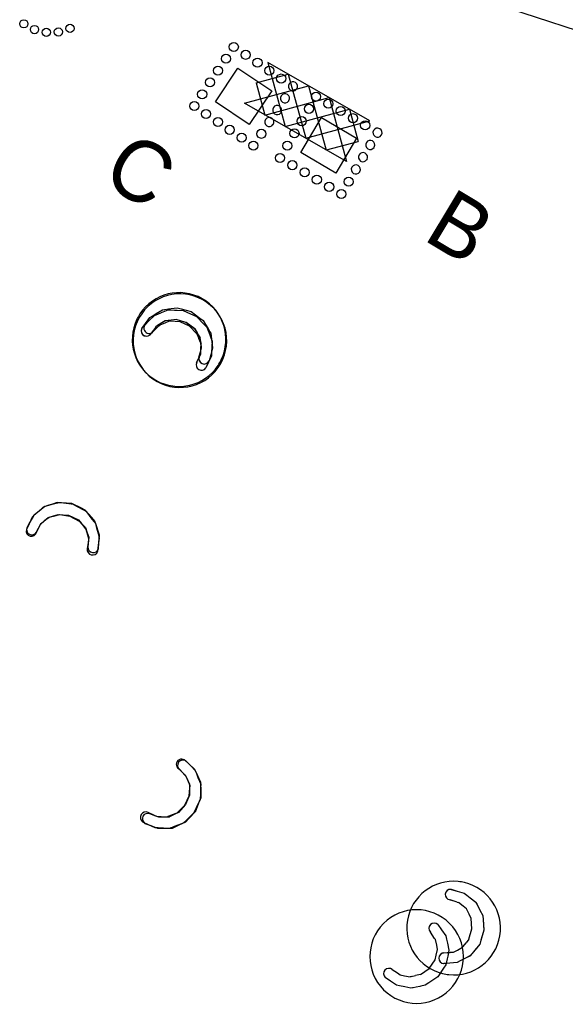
# Model space of a CAD drawing. Extents: x 2283629 to 2286552, y 529718 to 531440.
# Drawn here: x 2284499.9 to 2284634, y 530595.4 to 530837.2 of the extents above; entities that cross this region are included whole.
import ezdxf

# ---------------------------------------------------------------- set-up
doc = ezdxf.new("R2010")
doc.units = 0
for name, color, linetype in [('Draft_Corridor_Graphics_Final', 7, 'Continuous'), ('Draft_RDY_Construction_Class_Element', 7, 'Continuous'), ('P_NCDOT_Terrain_Model_Contour_Major', 7, 'Continuous'), ('P_NCDOT_Terrain_Model_Contour_Minor', 7, 'Continuous'), ('P_NCDOT_Terrain_Model_Triangles', 7, 'Continuous'), ('P_NCDOT_Terrain_Points_Random', 7, 'Continuous'), ('P_NCDOT_Terrain_Void', 7, 'Continuous'), ('P_RDY_TC_Pvmt_Asphalt_Intermediate_Course', 7, 'Continuous'), ('P_RDY_TC_Pvmt_Asphalt_Surface_Course', 7, 'Continuous'), ('P_RDY_TC_Pvmt_Asphalt_Surface_Course_Wedge', 7, 'Continuous')]:
    doc.layers.add(name, color=color, linetype=linetype)

msp = doc.modelspace()

# ---------------------------------------------------------------- linework, layer by layer
at = {"layer": 'Draft_Corridor_Graphics_Final'}
for p, q in [((2284511.89, 530715.37), (2284511.9, 530715.36)), ((2284514.29, 530714.25), (2284515.1, 530713.38)), ((2284504.83, 530712.85), (2284504.97, 530713.15)), ((2284515.86, 530712.57), (2284516.02, 530712.4)), ((2284540.33, 530651.76), (2284540.58, 530651.53)), ((2284540.66, 530644.26), (2284540.66, 530644.25)), ((2284536.82, 530641.29), (2284536.61, 530641.19)), ((2284538.89, 530642.3), (2284537.82, 530641.78))]:
    msp.add_line(p, q, dxfattribs=at)
for points in [[(2284519.25, 530707.16), (2284519.36, 530708.7), (2284519.48, 530710.45), (2284519.24, 530711.22), (2284518.82, 530712.5), (2284518.36, 530713.94), (2284518.36, 530713.95), (2284518.11, 530714.22), (2284518, 530714.35), (2284517.52, 530714.9), (2284516.88, 530715.62), (2284516.72, 530715.79), (2284515.97, 530716.64), (2284515.04, 530717.09), (2284512.67, 530718.24), (2284512.66, 530718.24), (2284510.12, 530718.43), (2284509.08, 530718.5), (2284507.68, 530718.04), (2284507.05, 530717.84), (2284506.14, 530717.54), (2284506.07, 530717.51), (2284505.65, 530717.37), (2284505.61, 530717.36), (2284504.29, 530716.15), (2284503.54, 530715.47), (2284502.93, 530714.9), (2284502.16, 530713.25), (2284501.51, 530711.84)], [(2284504.02, 530711.17), (2284504.83, 530712.85), (2284504.97, 530713.15), (2284506.07, 530714.14), (2284506.83, 530714.83), (2284508.21, 530715.25), (2284509.36, 530715.6), (2284511.89, 530715.37), (2284511.9, 530715.36), (2284514.29, 530714.25), (2284515.1, 530713.38), (2284515.86, 530712.57), (2284516.02, 530712.4), (2284516.48, 530711.02), (2284516.83, 530709.98), (2284516.77, 530709.19), (2284516.64, 530707.64), (2284516.64, 530707.64)], [(2284530.65, 530639.64), (2284532.09, 530639.09), (2284533.73, 530638.45), (2284534.54, 530638.46), (2284535.88, 530638.48), (2284537.39, 530638.5), (2284537.4, 530638.5), (2284537.73, 530638.65), (2284537.89, 530638.72), (2284538.56, 530639.02), (2284539.43, 530639.42), (2284539.65, 530639.52), (2284540.68, 530639.99), (2284541.38, 530640.74), (2284543.17, 530642.67), (2284543.18, 530642.68), (2284544.11, 530645.06), (2284544.49, 530646.03), (2284544.46, 530647.49), (2284544.45, 530648.16), (2284544.43, 530649.11), (2284544.43, 530649.19), (2284544.42, 530649.63), (2284544.42, 530649.67), (2284543.65, 530651.29), (2284543.22, 530652.21), (2284542.86, 530652.96), (2284541.51, 530654.18), (2284540.35, 530655.22)], [(2284538.97, 530653.02), (2284540.33, 530651.76), (2284540.58, 530651.53), (2284541.21, 530650.19), (2284541.64, 530649.26), (2284541.64, 530647.81), (2284541.63, 530646.61), (2284540.66, 530644.26), (2284540.66, 530644.25), (2284538.89, 530642.3), (2284537.82, 530641.78), (2284536.82, 530641.29), (2284536.61, 530641.19), (2284535.16, 530641.15), (2284534.06, 530641.13), (2284533.32, 530641.42), (2284531.88, 530642), (2284531.88, 530642)]]:
    msp.add_lwpolyline(points, dxfattribs=at)
for centre, radius, start, end in [((2284502.76, 530711.5), 1.3, 165.0476, 345.0476), ((2284517.97, 530707.5), 1.33, 173.9349, 345.0476), ((2284539.66, 530654.12), 1.3, 57.9198, 237.9198), ((2284531.35, 530640.77), 1.33, 66.8072, 237.9198)]:
    msp.add_arc(centre, radius, start, end, dxfattribs=at)
at = {"layer": 'P_NCDOT_Terrain_Model_Contour_Major'}
for p, q in [((2284533.33, 530761.61), (2284533.52, 530761.88)), ((2284533.34, 530761.61), (2284533.53, 530761.88)), ((2284534.79, 530762.65), (2284533.52, 530761.88)), ((2284534.8, 530762.65), (2284533.53, 530761.88)), ((2284535.67, 530763.19), (2284534.79, 530762.65)), ((2284535.68, 530763.18), (2284534.8, 530762.65)), ((2284537.1, 530763.34), (2284535.67, 530763.19)), ((2284537.11, 530763.33), (2284535.68, 530763.18)), ((2284538.3, 530763.46), (2284537.1, 530763.34)), ((2284538.31, 530763.46), (2284537.11, 530763.33)), ((2284540.74, 530762.76), (2284538.3, 530763.46)), ((2284540.75, 530762.75), (2284538.31, 530763.46)), ((2284540.74, 530762.76), (2284540.75, 530762.75)), ((2284540.75, 530762.75), (2284540.76, 530762.75)), ((2284542.88, 530761.21), (2284540.75, 530762.75)), ((2284542.89, 530761.2), (2284540.76, 530762.75)), ((2284533.33, 530761.61), (2284532.22, 530760.12)), ((2284533.34, 530761.61), (2284532.23, 530760.12)), ((2284542.88, 530761.21), (2284543.52, 530760.2)), ((2284542.89, 530761.2), (2284543.53, 530760.2)), ((2284544.11, 530759.26), (2284543.52, 530760.2)), ((2284544.12, 530759.26), (2284543.53, 530760.2)), ((2284544.11, 530759.26), (2284544.24, 530759.06)), ((2284544.12, 530759.26), (2284544.25, 530759.06)), ((2284544.43, 530757.62), (2284544.24, 530759.06)), ((2284544.44, 530757.62), (2284544.25, 530759.06)), ((2284544.58, 530756.53), (2284544.43, 530757.62)), ((2284544.59, 530756.52), (2284544.44, 530757.62)), ((2284543.94, 530754.27), (2284544.36, 530755.77)), ((2284543.95, 530754.27), (2284544.37, 530755.76)), ((2284544.36, 530755.77), (2284544.58, 530756.53)), ((2284544.37, 530755.76), (2284544.59, 530756.52)), ((2284607.43, 530620.3), (2284605.64, 530620.83)), ((2284607.43, 530620.31), (2284605.65, 530620.84)), ((2284607.43, 530620.31), (2284607.75, 530620.22)), ((2284607.43, 530620.3), (2284607.75, 530620.2)), ((2284608.9, 530619.29), (2284607.75, 530620.22)), ((2284608.9, 530619.28), (2284607.75, 530620.2)), ((2284609.71, 530618.65), (2284608.9, 530619.29)), ((2284609.71, 530618.64), (2284608.9, 530619.28)), ((2284610.34, 530617.35), (2284609.71, 530618.65)), ((2284610.34, 530617.34), (2284609.71, 530618.64)), ((2284610.87, 530616.27), (2284610.34, 530617.35)), ((2284610.87, 530616.26), (2284610.34, 530617.34)), ((2284611.04, 530613.73), (2284610.87, 530616.27)), ((2284611.04, 530613.72), (2284610.87, 530616.26)), ((2284610.31, 530611.19), (2284611.04, 530613.72)), ((2284610.31, 530611.18), (2284611.03, 530613.71)), ((2284611.04, 530613.72), (2284611.03, 530613.71)), ((2284611.04, 530613.73), (2284611.04, 530613.72)), ((2284608.9, 530609.36), (2284609.59, 530610.24)), ((2284608.91, 530609.37), (2284609.59, 530610.25)), ((2284610.31, 530611.19), (2284609.59, 530610.25)), ((2284610.31, 530611.18), (2284609.59, 530610.24)), ((2284604.16, 530607.82), (2284605.71, 530607.94)), ((2284604.16, 530607.81), (2284605.71, 530607.93)), ((2284605.71, 530607.94), (2284606.5, 530608)), ((2284605.71, 530607.93), (2284606.5, 530607.99)), ((2284606.5, 530608), (2284607.48, 530608.51)), ((2284606.5, 530607.99), (2284607.47, 530608.5)), ((2284607.47, 530608.5), (2284608.76, 530609.18)), ((2284607.48, 530608.51), (2284608.76, 530609.19)), ((2284608.91, 530609.37), (2284608.76, 530609.19)), ((2284608.9, 530609.36), (2284608.76, 530609.18))]:
    msp.add_line(p, q, dxfattribs=at)
for points in [[(2284529.88, 530761.25), (2284530.79, 530762.52), (2284531.85, 530763.99), (2284532.56, 530764.43), (2284533.42, 530764.96), (2284534.95, 530765.9), (2284534.99, 530765.9), (2284535.43, 530765.96), (2284535.51, 530765.97), (2284536.45, 530766.09), (2284537.11, 530766.18), (2284538.57, 530766.36), (2284539.57, 530766.09), (2284542.04, 530765.43), (2284542.05, 530765.42), (2284544.16, 530763.85), (2284544.99, 530763.24), (2284545.56, 530762.26), (2284545.69, 530762.06), (2284546.18, 530761.23), (2284546.55, 530760.6), (2284546.63, 530760.45), (2284546.82, 530760.14), (2284546.82, 530760.13), (2284547.01, 530758.63), (2284547.17, 530757.3), (2284547.27, 530756.49), (2284546.82, 530754.8), (2284546.42, 530753.3)], [(2284529.89, 530761.25), (2284530.8, 530762.51), (2284531.86, 530763.99), (2284532.57, 530764.43), (2284533.43, 530764.95), (2284534.96, 530765.89), (2284535, 530765.9), (2284535.44, 530765.96), (2284535.52, 530765.97), (2284536.46, 530766.09), (2284537.12, 530766.17), (2284538.58, 530766.36), (2284539.58, 530766.09), (2284542.05, 530765.42), (2284542.06, 530765.42), (2284544.17, 530763.85), (2284545, 530763.23), (2284545.58, 530762.26), (2284545.7, 530762.05), (2284546.19, 530761.23), (2284546.56, 530760.6), (2284546.64, 530760.45), (2284546.83, 530760.13), (2284546.83, 530760.13), (2284547.02, 530758.63), (2284547.18, 530757.29), (2284547.28, 530756.49), (2284546.83, 530754.79), (2284546.43, 530753.3)], [(2284605.91, 530623.41), (2284607.41, 530622.99), (2284609.16, 530622.5), (2284609.81, 530621.98), (2284610.61, 530621.35), (2284612.01, 530620.24), (2284612.03, 530620.2), (2284612.23, 530619.81), (2284612.27, 530619.74), (2284612.71, 530618.89), (2284613.01, 530618.3), (2284613.68, 530617), (2284613.78, 530615.96), (2284613.99, 530613.42), (2284613.99, 530613.41), (2284613.24, 530610.88), (2284612.94, 530609.9), (2284612.22, 530609.02), (2284612.07, 530608.84), (2284611.46, 530608.09), (2284611, 530607.53), (2284610.89, 530607.4), (2284610.66, 530607.11), (2284610.65, 530607.11), (2284609.3, 530606.42), (2284608.11, 530605.82), (2284607.39, 530605.45), (2284605.64, 530605.29), (2284604.09, 530605.15)], [(2284605.91, 530623.43), (2284607.41, 530623), (2284609.16, 530622.51), (2284609.81, 530621.99), (2284610.61, 530621.36), (2284612.01, 530620.25), (2284612.03, 530620.21), (2284612.23, 530619.82), (2284612.27, 530619.75), (2284612.71, 530618.9), (2284613.01, 530618.31), (2284613.69, 530617.01), (2284613.78, 530615.97), (2284613.99, 530613.43), (2284613.99, 530613.42), (2284613.24, 530610.89), (2284612.94, 530609.91), (2284612.22, 530609.03), (2284612.07, 530608.85), (2284611.46, 530608.1), (2284611, 530607.54), (2284610.89, 530607.41), (2284610.66, 530607.12), (2284610.65, 530607.12), (2284609.31, 530606.44), (2284608.11, 530605.83), (2284607.39, 530605.46), (2284605.64, 530605.3), (2284604.1, 530605.16)]]:
    msp.add_lwpolyline(points, dxfattribs=at)
for centre, radius, start, end in [((2284539.06, 530758.6), 11.5, 334.1603, 146.8069), ((2284539.04, 530758.55), 11.5, 146.5657, 154.1603), ((2284539.04, 530758.55), 11.5, 154.1603, 326.5657), ((2284531.05, 530760.69), 1.3, 154.1603, 334.1603), ((2284531.06, 530760.68), 1.3, 154.1603, 334.1603), ((2284545.22, 530753.88), 1.33, 163.0477, 334.1603), ((2284545.23, 530753.88), 1.33, 163.0477, 334.1603), ((2284539.06, 530758.6), 11.5, 326.3245, 334.1603), ((2284606.51, 530613.9), 11.5, 84.1603, 256.5657), ((2284606.55, 530613.89), 11.5, 264.1603, 76.8069), ((2284606.51, 530613.9), 11.5, 76.5657, 84.1603), ((2284605.78, 530622.13), 1.3, 84.1603, 264.1603), ((2284605.78, 530622.12), 1.3, 84.1603, 264.1603), ((2284604.23, 530606.48), 1.33, 93.0477, 264.1603), ((2284604.23, 530606.49), 1.33, 93.0477, 264.1603), ((2284606.55, 530613.89), 11.5, 256.3245, 264.1603)]:
    msp.add_arc(centre, radius, start, end, dxfattribs=at)
at = {"layer": 'P_NCDOT_Terrain_Model_Contour_Minor'}
for p, q in [((2284534.09, 530761.91), (2284532.75, 530760.61)), ((2284534.09, 530761.91), (2284532.75, 530760.61)), ((2284534.09, 530761.91), (2284534.33, 530762.14)), ((2284534.09, 530761.91), (2284534.33, 530762.14)), ((2284535.7, 530762.69), (2284534.33, 530762.14)), ((2284535.7, 530762.69), (2284534.33, 530762.14)), ((2284536.65, 530763.08), (2284535.7, 530762.69)), ((2284536.65, 530763.08), (2284535.7, 530762.69)), ((2284538.1, 530763), (2284536.65, 530763.08)), ((2284538.1, 530763), (2284536.65, 530763.08)), ((2284539.3, 530762.93), (2284538.1, 530763)), ((2284539.3, 530762.93), (2284538.1, 530763)), ((2284541.59, 530761.83), (2284539.3, 530762.93)), ((2284541.59, 530761.83), (2284539.3, 530762.93)), ((2284541.59, 530761.83), (2284541.6, 530761.82)), ((2284541.59, 530761.83), (2284541.6, 530761.82)), ((2284543.45, 530759.95), (2284541.6, 530761.82)), ((2284543.45, 530759.95), (2284541.6, 530761.82)), ((2284543.45, 530759.95), (2284543.92, 530758.86)), ((2284543.45, 530759.95), (2284543.92, 530758.86)), ((2284544.35, 530757.83), (2284543.92, 530758.86)), ((2284544.35, 530757.83), (2284543.92, 530758.86)), ((2284544.35, 530757.83), (2284544.44, 530757.62)), ((2284544.35, 530757.83), (2284544.44, 530757.62)), ((2284544.4, 530756.17), (2284544.44, 530757.62)), ((2284544.4, 530756.17), (2284544.44, 530757.62)), ((2284544.03, 530754.35), (2284544.36, 530755.06)), ((2284544.03, 530754.35), (2284544.36, 530755.06)), ((2284544.36, 530755.06), (2284544.4, 530756.17)), ((2284544.36, 530755.06), (2284544.4, 530756.17)), ((2284543.37, 530752.94), (2284544.03, 530754.35)), ((2284543.37, 530752.94), (2284544.03, 530754.35)), ((2284601.87, 530611.38), (2284600.82, 530612.92)), ((2284601.87, 530611.38), (2284600.82, 530612.92)), ((2284601.87, 530611.38), (2284602.06, 530611.11)), ((2284601.87, 530611.38), (2284602.06, 530611.11)), ((2284602.37, 530609.66), (2284602.06, 530611.11)), ((2284602.37, 530609.66), (2284602.06, 530611.11)), ((2284602.59, 530608.66), (2284602.37, 530609.66)), ((2284602.59, 530608.66), (2284602.37, 530609.66)), ((2284601.99, 530606.08), (2284602.26, 530607.25)), ((2284601.99, 530606.08), (2284602.26, 530607.25)), ((2284602.26, 530607.25), (2284602.59, 530608.66)), ((2284602.26, 530607.25), (2284602.59, 530608.66)), ((2284600.52, 530604), (2284601.99, 530606.08)), ((2284600.52, 530604), (2284601.99, 530606.08)), ((2284591.46, 530603.75), (2284592.73, 530602.87)), ((2284591.46, 530603.75), (2284592.73, 530602.87)), ((2284592.73, 530602.87), (2284593.38, 530602.42)), ((2284592.73, 530602.87), (2284593.38, 530602.42)), ((2284593.38, 530602.42), (2284594.46, 530602.2)), ((2284593.38, 530602.42), (2284594.46, 530602.2)), ((2284594.46, 530602.2), (2284595.89, 530601.91)), ((2284594.46, 530602.2), (2284595.89, 530601.91)), ((2284596.11, 530601.96), (2284597.2, 530602.21)), ((2284596.11, 530601.96), (2284597.2, 530602.21)), ((2284598.36, 530602.49), (2284597.2, 530602.21)), ((2284598.36, 530602.49), (2284597.2, 530602.21)), ((2284598.36, 530602.49), (2284600.51, 530604)), ((2284598.36, 530602.49), (2284600.51, 530604)), ((2284600.52, 530604), (2284600.51, 530604)), ((2284600.52, 530604), (2284600.51, 530604)), ((2284596.11, 530601.96), (2284595.89, 530601.91)), ((2284596.11, 530601.96), (2284595.89, 530601.91))]:
    msp.add_line(p, q, dxfattribs=at)
for points in [[(2284530.63, 530762.11), (2284531.73, 530763.21), (2284533.02, 530764.49), (2284533.79, 530764.81), (2284534.73, 530765.19), (2284536.39, 530765.87), (2284536.43, 530765.87), (2284536.87, 530765.85), (2284536.95, 530765.85), (2284537.9, 530765.82), (2284538.57, 530765.8), (2284540.03, 530765.74), (2284540.98, 530765.31), (2284543.3, 530764.26), (2284543.31, 530764.25), (2284545.14, 530762.36), (2284545.86, 530761.61), (2284546.27, 530760.56), (2284546.36, 530760.34), (2284546.71, 530759.44), (2284546.97, 530758.76), (2284547.03, 530758.6), (2284547.17, 530758.26), (2284547.17, 530758.25), (2284547.1, 530756.74), (2284547.05, 530755.4), (2284547.01, 530754.59), (2284546.29, 530752.99), (2284545.66, 530751.58)], [(2284530.63, 530762.11), (2284531.73, 530763.21), (2284533.02, 530764.49), (2284533.79, 530764.81), (2284534.73, 530765.19), (2284536.39, 530765.87), (2284536.43, 530765.87), (2284536.87, 530765.85), (2284536.95, 530765.85), (2284537.9, 530765.82), (2284538.57, 530765.8), (2284540.03, 530765.74), (2284540.98, 530765.31), (2284543.3, 530764.26), (2284543.31, 530764.25), (2284545.14, 530762.36), (2284545.86, 530761.61), (2284546.27, 530760.56), (2284546.36, 530760.34), (2284546.71, 530759.44), (2284546.97, 530758.76), (2284547.03, 530758.6), (2284547.17, 530758.26), (2284547.17, 530758.25), (2284547.1, 530756.74), (2284547.05, 530755.4), (2284547.01, 530754.59), (2284546.29, 530752.99), (2284545.66, 530751.58)], [(2284602.65, 530614.76), (2284603.55, 530613.48), (2284604.6, 530612), (2284604.78, 530611.18), (2284605, 530610.2), (2284605.38, 530608.44), (2284605.38, 530608.4), (2284605.29, 530607.97), (2284605.27, 530607.9), (2284605.08, 530606.96), (2284604.94, 530606.31), (2284604.64, 530604.88), (2284604.06, 530604.01), (2284602.62, 530601.9), (2284602.62, 530601.9), (2284600.43, 530600.41), (2284599.58, 530599.83), (2284598.48, 530599.61), (2284598.24, 530599.56), (2284597.3, 530599.37), (2284596.59, 530599.22), (2284596.42, 530599.19), (2284596.06, 530599.11), (2284596.05, 530599.11), (2284594.57, 530599.43), (2284593.26, 530599.71), (2284592.47, 530599.89), (2284591.01, 530600.87), (2284589.73, 530601.73)], [(2284602.65, 530614.76), (2284603.55, 530613.48), (2284604.6, 530612), (2284604.78, 530611.18), (2284605, 530610.2), (2284605.38, 530608.44), (2284605.38, 530608.4), (2284605.29, 530607.97), (2284605.27, 530607.9), (2284605.08, 530606.96), (2284604.94, 530606.31), (2284604.64, 530604.88), (2284604.06, 530604.01), (2284602.62, 530601.9), (2284602.62, 530601.9), (2284600.43, 530600.41), (2284599.58, 530599.83), (2284598.48, 530599.61), (2284598.24, 530599.56), (2284597.3, 530599.37), (2284596.59, 530599.22), (2284596.42, 530599.19), (2284596.06, 530599.11), (2284596.05, 530599.11), (2284594.57, 530599.43), (2284593.26, 530599.71), (2284592.47, 530599.89), (2284591.01, 530600.87), (2284589.73, 530601.73)]]:
    msp.add_lwpolyline(points, dxfattribs=at)
for centre, radius, start, end in [((2284539.26, 530758.3), 11.5, 54.8206, 144.8206), ((2284539.26, 530758.3), 11.5, 324.8206, 54.8206), ((2284539.26, 530758.3), 11.5, 144.8206, 234.8206), ((2284531.69, 530761.36), 1.3, 144.8206, 324.8206), ((2284531.69, 530761.36), 1.3, 144.8206, 324.8206), ((2284544.57, 530752.35), 1.33, 153.708, 324.8206), ((2284544.57, 530752.35), 1.33, 153.708, 324.8206), ((2284539.26, 530758.3), 11.5, 234.8206, 324.8206), ((2284597.44, 530606.9), 11.5, 45.0567, 135.0567), ((2284597.44, 530606.9), 11.5, 135.0567, 225.0567), ((2284601.74, 530613.84), 1.3, 45.0567, 225.0567), ((2284601.74, 530613.84), 1.3, 45.0567, 225.0567), ((2284597.44, 530606.9), 11.5, 315.0567, 45.0567), ((2284590.67, 530602.68), 1.33, 53.9441, 225.0567), ((2284590.67, 530602.68), 1.33, 53.9441, 225.0567), ((2284597.44, 530606.9), 11.5, 225.0567, 315.0567)]:
    msp.add_arc(centre, radius, start, end, dxfattribs=at)
at = {"layer": 'P_NCDOT_Terrain_Model_Triangles'}
for p, q in [((2284512.21, 530715.16), (2284512.22, 530715.15)), ((2284514.53, 530713.89), (2284515.29, 530712.98)), ((2284505, 530713.08), (2284505.17, 530713.37)), ((2284516, 530712.12), (2284516.15, 530711.94)), ((2284540.5, 530651.52), (2284540.73, 530651.27)), ((2284540.37, 530644.01), (2284540.36, 530644.01)), ((2284536.35, 530641.29), (2284536.13, 530641.2)), ((2284538.48, 530642.17), (2284537.38, 530641.71))]:
    msp.add_line(p, q, dxfattribs=at)
for points in [[(2284519.05, 530706.5), (2284519.26, 530708.04), (2284519.48, 530709.78), (2284519.29, 530710.57), (2284518.95, 530711.87), (2284518.58, 530713.33), (2284518.58, 530713.34), (2284518.35, 530713.63), (2284518.25, 530713.76), (2284517.8, 530714.34), (2284517.21, 530715.1), (2284517.06, 530715.28), (2284516.37, 530716.18), (2284515.47, 530716.68), (2284513.17, 530717.97), (2284513.16, 530717.98), (2284510.63, 530718.32), (2284509.6, 530718.46), (2284508.18, 530718.09), (2284507.54, 530717.92), (2284506.61, 530717.68), (2284506.54, 530717.66), (2284506.11, 530717.55), (2284506.07, 530717.54), (2284504.68, 530716.41), (2284503.89, 530715.78), (2284503.24, 530715.25), (2284502.37, 530713.65), (2284501.63, 530712.28)], [(2284504.09, 530711.46), (2284505, 530713.08), (2284505.17, 530713.37), (2284506.32, 530714.3), (2284507.12, 530714.94), (2284508.53, 530715.27), (2284509.7, 530715.55), (2284512.21, 530715.16), (2284512.22, 530715.15), (2284514.53, 530713.89), (2284515.29, 530712.98), (2284516, 530712.12), (2284516.15, 530711.94), (2284516.53, 530710.54), (2284516.81, 530709.47), (2284516.7, 530708.69), (2284516.47, 530707.15), (2284516.47, 530707.15)], [(2284530.08, 530640.03), (2284531.49, 530639.38), (2284533.09, 530638.65), (2284533.9, 530638.61), (2284535.24, 530638.54), (2284536.75, 530638.47), (2284536.75, 530638.47), (2284537.1, 530638.6), (2284537.26, 530638.66), (2284537.94, 530638.92), (2284538.84, 530639.26), (2284539.06, 530639.34), (2284540.12, 530639.75), (2284540.86, 530640.46), (2284542.77, 530642.27), (2284542.78, 530642.28), (2284543.86, 530644.6), (2284544.29, 530645.54), (2284544.36, 530647.01), (2284544.39, 530647.67), (2284544.43, 530648.63), (2284544.43, 530648.7), (2284544.45, 530649.14), (2284544.45, 530649.18), (2284543.78, 530650.85), (2284543.41, 530651.79), (2284543.1, 530652.56), (2284541.83, 530653.86), (2284540.73, 530654.97)], [(2284539.22, 530652.86), (2284540.5, 530651.52), (2284540.73, 530651.27), (2284541.28, 530649.9), (2284541.66, 530648.94), (2284541.56, 530647.5), (2284541.48, 530646.3), (2284540.37, 530644.01), (2284540.36, 530644.01), (2284538.48, 530642.17), (2284537.38, 530641.71), (2284536.35, 530641.29), (2284536.13, 530641.2), (2284534.68, 530641.25), (2284533.58, 530641.3), (2284532.86, 530641.63), (2284531.46, 530642.3), (2284531.46, 530642.3)]]:
    msp.add_lwpolyline(points, dxfattribs=at)
for centre, radius, start, end in [((2284502.86, 530711.87), 1.3, 161.4882, 341.4882), ((2284517.79, 530706.93), 1.33, 170.3755, 341.4882), ((2284539.98, 530653.92), 1.3, 54.3604, 234.3604), ((2284530.86, 530641.11), 1.33, 63.2478, 234.3604)]:
    msp.add_arc(centre, radius, start, end, dxfattribs=at)
at = {"layer": 'P_NCDOT_Terrain_Points_Random'}
msp.add_lwpolyline([(2284603.92, 530849.87), (2284606.71, 530844.47), (2284636.9, 530834.54), (2284715.51, 530802.89), (2284733.68, 530793.16), (2284744.13, 530816.82)], dxfattribs=at)
at = {"layer": 'P_NCDOT_Terrain_Void'}
for p, q in [((2284560.86, 530826.66), (2284565.16, 530810.9)), ((2284585.95, 530812.32), (2284560.86, 530826.66)), ((2284557.97, 530821.63), (2284565.9, 530823.79)), ((2284565.9, 530823.79), (2284570.19, 530808.03)), ((2284555.13, 530816.64), (2284570.89, 530820.93)), ((2284557.97, 530821.63), (2284560.16, 530813.75)), ((2284570.89, 530820.93), (2284575.23, 530805.15)), ((2284560.16, 530813.75), (2284575.92, 530818.05)), ((2284575.92, 530818.05), (2284580.22, 530802.3)), ((2284580.22, 530802.3), (2284555.13, 530816.64)), ((2284565.16, 530810.9), (2284580.96, 530815.18)), ((2284580.96, 530815.18), (2284583.08, 530807.28)), ((2284570.19, 530808.03), (2284585.95, 530812.32)), ((2284575.3, 530805.17), (2284583.08, 530807.28))]:
    msp.add_line(p, q, dxfattribs=at)
at = {"layer": 'P_RDY_TC_Pvmt_Asphalt_Intermediate_Course'}
for p, q in [((2284567.95, 530820.11), (2284568.02, 530820.2)), ((2284566.01, 530817.2), (2284566.07, 530817.29)), ((2284564.07, 530814.3), (2284564.12, 530814.37)), ((2284562.13, 530811.4), (2284562.17, 530811.45)), ((2284588.76, 530808.81), (2284588.81, 530808.9)), ((2284586.99, 530805.8), (2284587.04, 530805.88)), ((2284585.22, 530802.78), (2284585.26, 530802.86)), ((2284583.45, 530799.77), (2284583.49, 530799.83))]:
    msp.add_line(p, q, dxfattribs=at)
for points in [[(2284553.53, 530825.28), (2284561.85, 530819.72), (2284556.29, 530811.41), (2284547.98, 530816.98)], [(2284574.06, 530813.14), (2284582.68, 530808.07), (2284577.62, 530799.45), (2284569, 530804.52)]]:
    msp.add_lwpolyline(points, close=True, dxfattribs=at)
for centre in [(2284552.5, 530830.5), (2284555.41, 530828.56), (2284550.56, 530827.59), (2284558.32, 530826.61), (2284548.61, 530824.68), (2284561.23, 530824.67), (2284546.67, 530821.77), (2284564.14, 530822.72), (2284544.72, 530818.86), (2284572.73, 530818.29), (2284575.75, 530816.52), (2284542.78, 530815.95), (2284545.69, 530814.01), (2284570.96, 530815.27), (2284578.77, 530814.74), (2284548.6, 530812.06), (2284569.18, 530812.25), (2284581.78, 530812.97), (2284551.51, 530810.12), (2284559.27, 530809.14), (2284567.41, 530809.23), (2284584.8, 530811.2), (2284554.42, 530808.17), (2284557.33, 530806.23), (2284565.64, 530806.22), (2284563.87, 530803.2), (2284566.88, 530801.43), (2284569.9, 530799.65), (2284572.92, 530797.88), (2284580.73, 530797.35), (2284575.94, 530796.11), (2284578.96, 530794.33)]:
    msp.add_circle(centre, 1.12, dxfattribs=at)
for centre, start, end in [((2284567.05, 530820.78), 329.0561, 323.4402), ((2284565.11, 530817.87), 328.7596, 323.7367), ((2284563.16, 530814.96), 328.4231, 324.0732), ((2284561.22, 530812.05), 328.024, 324.4724), ((2284587.82, 530809.42), 332.3818, 326.7659), ((2284586.05, 530806.41), 332.0853, 327.0624), ((2284584.27, 530803.39), 331.7488, 327.3989), ((2284582.5, 530800.37), 331.3496, 327.7981)]:
    msp.add_arc(centre, 1.12, start, end, dxfattribs=at)
at = {"layer": 'P_RDY_TC_Pvmt_Asphalt_Surface_Course_Wedge'}
for centre in [(2284500.88, 530836.17), (2284503.5, 530834.76), (2284506.41, 530834.08), (2284509.39, 530834.18), (2284512.24, 530835.04)]:
    msp.add_circle(centre, 1.01, dxfattribs=at)

# ---------------------------------------------------------------- texts
at = {"layer": 'Draft_RDY_Construction_Class_Element'}
msp.add_text('B', height=15, rotation=329.0088, dxfattribs=at).set_placement((2284598.69, 530783.3))
at = {"layer": 'P_RDY_TC_Pvmt_Asphalt_Surface_Course'}
msp.add_text('C', height=15, rotation=329.1861, dxfattribs=at).set_placement((2284519.5, 530797.4))

doc.saveas('drawing.dxf')
